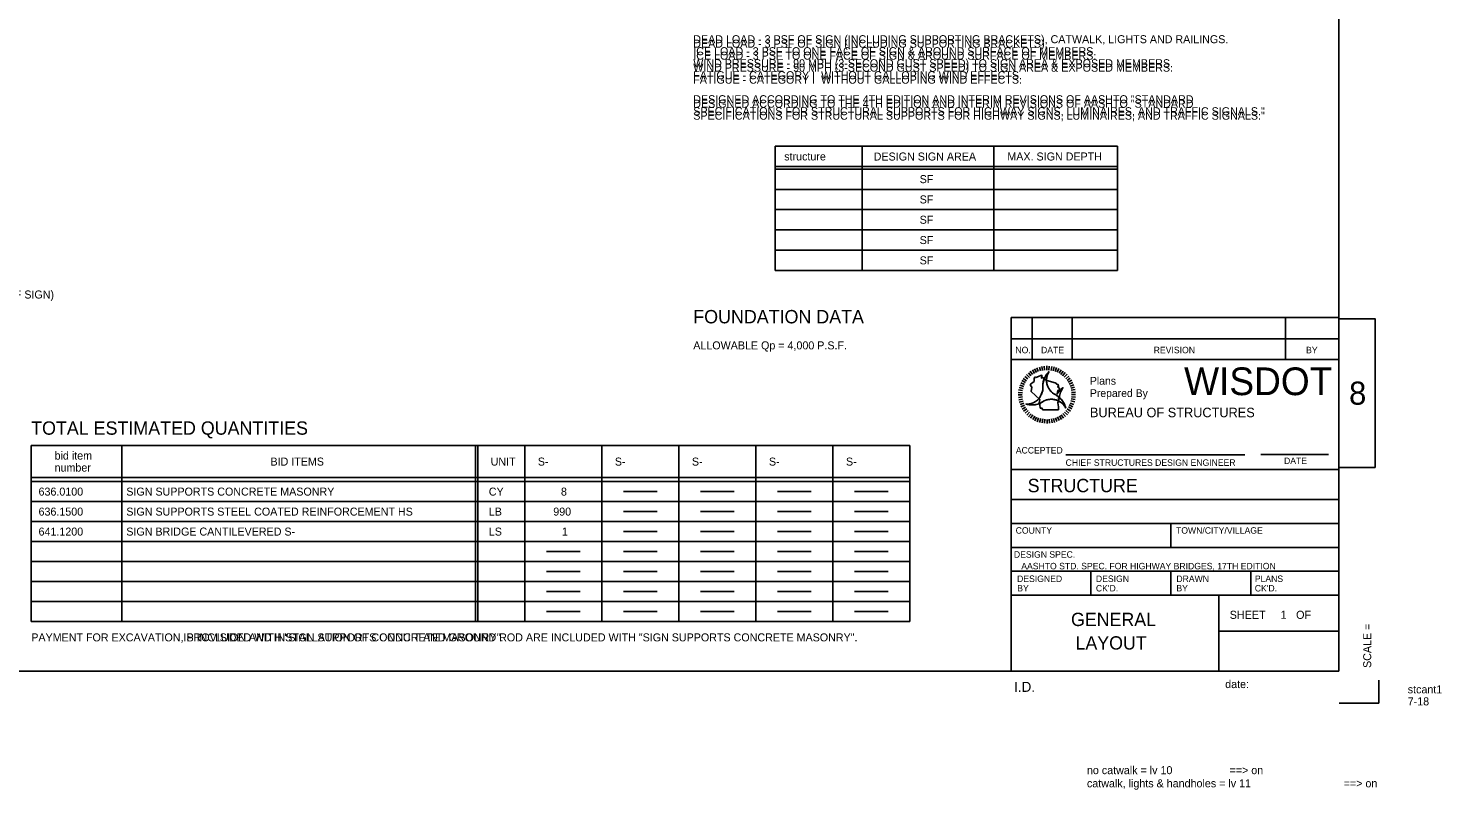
# Model space of a CAD drawing. Extents: x -21 to 58.5, y -15.2 to 40.8.
# Drawn here: x 8.74 to 58.43, y -15.18 to 11.57 of the extents above; entities that cross this region are included whole.
import ezdxf

# ---------------------------------------------------------------- set-up
doc = ezdxf.new("R2010")
doc.units = 0
for name, color, linetype in [('Level 1', 7, 'Continuous'), ('Level 10', 7, 'Continuous'), ('Level 11', 7, 'Continuous'), ('Level 2', 7, 'Continuous')]:
    doc.layers.add(name, color=color, linetype=linetype)

msp = doc.modelspace()

# ---------------------------------------------------------------- linework, layer by layer
at = {"layer": 'Level 1'}
for p, q in [((54.804, -11.023), (54.804, 36.226)), ((43.286, -0.07), (43.286, 1.405)), ((43.286, 1.405), (54.804, 1.405)), ((44.035, -0.07), (44.035, 1.405)), ((45.44, -0.07), (45.44, 1.405)), ((52.931, -0.07), (52.931, 1.405)), ((43.286, 0.657), (54.811, 0.657)), ((43.286, -11.023), (43.286, -0.07)), ((43.286, -0.07), (54.811, -0.07)), ((45.214, -3.422), (51.51, -3.422)), ((52.069, -3.407), (54.447, -3.407)), ((43.286, -3.929), (54.811, -3.929)), ((43.286, -4.982), (54.811, -4.982)), ((43.286, -5.824), (54.811, -5.824)), ((48.905, -5.824), (48.905, -6.667)), ((43.286, -6.667), (54.804, -6.667)), ((43.286, -7.51), (54.804, -7.51)), ((46.095, -7.51), (46.095, -8.353)), ((48.905, -7.51), (48.905, -8.353)), ((51.714, -7.51), (51.714, -8.353)), ((43.286, -8.353), (54.811, -8.353)), ((50.59, -11.023), (50.59, -8.354)), ((50.592, -9.618), (54.804, -9.618)), ((-15.791, -11.023), (54.804, -11.023)), ((56.21, -12.148), (56.21, -11.332)), ((54.821, -12.148), (56.21, -12.148))]:
    msp.add_line(p, q, dxfattribs=at)
msp.add_lwpolyline([(54.804, 1.363), (56.081, 1.363), (56.081, -3.86), (54.804, -3.86)], close=True, dxfattribs=at)
at = {"layer": 'Level 2'}
for p, q in [((34.99, 7.429), (34.99, 3.058)), ((34.99, 7.429), (47.025, 7.429)), ((38.059, 7.429), (38.059, 3.058)), ((42.685, 7.429), (42.685, 3.058)), ((47.025, 7.429), (47.025, 3.058)), ((34.99, 6.715), (47.025, 6.715)), ((34.99, 6.627), (47.025, 6.627)), ((34.99, 5.913), (47.025, 5.913)), ((34.99, 5.199), (47.025, 5.199)), ((34.99, 4.485), (47.025, 4.485)), ((34.99, 3.771), (47.025, 3.771)), ((34.99, 3.058), (47.025, 3.058)), ((44.046, -0.596), (43.965, -0.48)), ((44.11, -0.556), (44.039, -0.432)), ((44.177, -0.519), (44.117, -0.391)), ((44.246, -0.491), (44.198, -0.356)), ((44.317, -0.467), (44.282, -0.331)), ((44.393, -0.45), (44.367, -0.311)), ((44.467, -0.44), (44.455, -0.299)), ((44.542, -0.437), (44.542, -0.294)), ((44.618, -0.439), (44.63, -0.298)), ((44.693, -0.448), (44.718, -0.308)), ((44.767, -0.465), (44.804, -0.327)), ((44.839, -0.487), (44.888, -0.353)), ((44.909, -0.516), (44.969, -0.386)), ((44.976, -0.549), (45.047, -0.427)), ((45.041, -0.59), (45.122, -0.473)), ((43.732, -1.011), (43.598, -0.964)), ((43.76, -0.942), (43.632, -0.881)), ((43.795, -0.874), (43.672, -0.804)), ((43.835, -0.811), (43.719, -0.729)), ((43.881, -0.75), (43.772, -0.659)), ((43.932, -0.694), (43.831, -0.593)), ((43.987, -0.643), (43.895, -0.533)), ((45.101, -0.636), (45.192, -0.527)), ((45.157, -0.686), (45.257, -0.586)), ((45.208, -0.742), (45.316, -0.651)), ((45.254, -0.802), (45.371, -0.72)), ((45.296, -0.865), (45.419, -0.794)), ((45.331, -0.932), (45.459, -0.872)), ((45.36, -1.001), (45.494, -0.953)), ((43.681, -1.309), (43.539, -1.309)), ((43.684, -1.233), (43.543, -1.221)), ((43.685, -1.384), (43.544, -1.396)), ((43.694, -1.158), (43.553, -1.133)), ((43.695, -1.458), (43.556, -1.484)), ((43.709, -1.084), (43.572, -1.048)), ((45.383, -1.073), (45.521, -1.037)), ((45.4, -1.147), (45.54, -1.122)), ((45.402, -1.448), (45.542, -1.473)), ((45.411, -1.222), (45.552, -1.209)), ((45.411, -1.373), (45.554, -1.385)), ((45.415, -1.298), (45.556, -1.298)), ((43.713, -1.532), (43.575, -1.569)), ((43.736, -1.605), (43.602, -1.653)), ((43.765, -1.674), (43.636, -1.734)), ((43.801, -1.741), (43.677, -1.812)), ((43.842, -1.805), (43.725, -1.886)), ((43.887, -1.864), (43.778, -1.955)), ((43.939, -1.919), (43.839, -2.02)), ((43.995, -1.97), (43.904, -2.079)), ((45.109, -1.963), (45.2, -2.072)), ((45.165, -1.912), (45.266, -2.012)), ((45.215, -1.856), (45.324, -1.947)), ((45.26, -1.795), (45.377, -1.877)), ((45.301, -1.732), (45.425, -1.802)), ((45.335, -1.665), (45.464, -1.725)), ((45.364, -1.595), (45.497, -1.643)), ((45.386, -1.523), (45.524, -1.559)), ((44.056, -2.016), (43.974, -2.132)), ((44.119, -2.056), (44.048, -2.179)), ((44.187, -2.091), (44.127, -2.22)), ((44.256, -2.119), (44.208, -2.253)), ((44.329, -2.142), (44.292, -2.279)), ((44.403, -2.157), (44.378, -2.297)), ((44.477, -2.167), (44.465, -2.308)), ((44.553, -2.169), (44.553, -2.311)), ((44.629, -2.166), (44.641, -2.308)), ((44.705, -2.156), (44.729, -2.295)), ((44.778, -2.138), (44.815, -2.276)), ((44.849, -2.115), (44.898, -2.249)), ((44.919, -2.086), (44.98, -2.214)), ((44.986, -2.05), (45.057, -2.173)), ((45.05, -2.01), (45.13, -2.126)), ((8.843, -9.278), (8.843, -3.091)), ((8.843, -9.278), (8.843, -3.091)), ((8.843, -9.278), (8.843, -3.091)), ((8.843, -9.278), (8.843, -3.091)), ((8.843, -9.278), (8.843, -3.091)), ((8.843, -9.278), (8.843, -3.091)), ((8.843, -9.278), (8.843, -3.091)), ((39.731, -3.091), (8.843, -3.091)), ((12.034, -9.278), (12.034, -3.091)), ((12.034, -9.278), (12.034, -3.091)), ((12.034, -9.278), (12.034, -3.091)), ((12.034, -9.278), (12.034, -3.091)), ((12.034, -9.278), (12.034, -3.091)), ((12.034, -9.278), (12.034, -3.091)), ((12.034, -9.278), (12.034, -3.091)), ((12.034, -9.278), (12.034, -3.091)), ((24.459, -9.278), (24.459, -3.091)), ((24.459, -9.278), (24.459, -3.091)), ((24.459, -9.278), (24.459, -3.091)), ((24.459, -9.278), (24.459, -3.091)), ((24.459, -9.278), (24.459, -3.091)), ((24.459, -9.278), (24.459, -3.091)), ((24.459, -9.278), (24.459, -3.091)), ((24.459, -9.278), (24.459, -3.091)), ((24.55, -9.278), (24.55, -3.091)), ((24.55, -9.278), (24.55, -3.091)), ((24.55, -9.278), (24.55, -3.091)), ((24.55, -9.278), (24.55, -3.091)), ((24.55, -9.278), (24.55, -3.091)), ((24.55, -9.278), (24.55, -3.091)), ((24.55, -9.278), (24.55, -3.091)), ((24.55, -9.278), (24.55, -3.091)), ((26.191, -9.278), (26.191, -3.091)), ((28.899, -9.278), (28.899, -3.091)), ((31.607, -9.278), (31.607, -3.091)), ((34.315, -9.278), (34.315, -3.091)), ((37.023, -9.278), (37.023, -3.091)), ((39.731, -9.278), (39.731, -3.091)), ((39.731, -4.216), (8.843, -4.216)), ((39.731, -4.356), (8.843, -4.356)), ((29.661, -4.708), (30.845, -4.708)), ((32.369, -4.708), (33.553, -4.708)), ((35.077, -4.708), (36.261, -4.708)), ((37.785, -4.708), (38.969, -4.708)), ((39.731, -5.06), (8.843, -5.06)), ((29.661, -5.411), (30.845, -5.411)), ((32.369, -5.411), (33.553, -5.411)), ((35.077, -5.411), (36.261, -5.411)), ((37.785, -5.411), (38.969, -5.411)), ((39.731, -5.762), (8.843, -5.762)), ((29.661, -6.114), (30.845, -6.114)), ((32.369, -6.114), (33.553, -6.114)), ((35.077, -6.114), (36.261, -6.114)), ((37.785, -6.114), (38.969, -6.114)), ((39.731, -6.466), (8.843, -6.466)), ((26.953, -6.817), (28.137, -6.817)), ((29.661, -6.817), (30.845, -6.817)), ((32.369, -6.817), (33.553, -6.817)), ((35.077, -6.817), (36.261, -6.817)), ((37.785, -6.817), (38.969, -6.817)), ((39.731, -7.168), (8.843, -7.168)), ((39.731, -7.872), (8.843, -7.872)), ((26.953, -7.52), (28.137, -7.52)), ((29.661, -7.52), (30.845, -7.52)), ((32.369, -7.52), (33.553, -7.52)), ((35.077, -7.52), (36.261, -7.52)), ((37.785, -7.52), (38.969, -7.52)), ((26.953, -8.223), (28.137, -8.223)), ((29.661, -8.223), (30.845, -8.223)), ((32.369, -8.223), (33.553, -8.223)), ((35.077, -8.223), (36.261, -8.223)), ((37.785, -8.223), (38.969, -8.223)), ((39.731, -8.575), (8.843, -8.575)), ((26.953, -8.926), (28.137, -8.926)), ((29.661, -8.926), (30.845, -8.926)), ((32.369, -8.926), (33.553, -8.926)), ((35.077, -8.926), (36.261, -8.926)), ((37.785, -8.926), (38.969, -8.926)), ((39.731, -9.278), (8.843, -9.278))]:
    msp.add_line(p, q, dxfattribs=at)
msp.add_lwpolyline([(44.625, -0.491), (44.535, -0.594), (44.476, -0.702), (44.427, -0.837), (44.4, -0.943), (44.403, -1.073), (44.4, -1.158), (44.375, -1.236), (44.349, -1.295), (44.328, -1.346), (44.297, -1.403), (44.248, -1.46), (44.212, -1.491), (44.144, -1.547), (44.088, -1.575), (44.064, -1.589), (43.99, -1.614), (43.92, -1.631), (43.825, -1.636), (43.812, -1.635), (43.857, -1.646), (43.921, -1.658), (43.979, -1.661), (44.029, -1.663), (44.074, -1.661), (44.133, -1.654), (44.176, -1.645), (44.223, -1.633), (44.282, -1.613), (44.334, -1.589), (44.371, -1.571), (44.45, -1.518), (44.51, -1.494), (44.539, -1.484), (44.59, -1.474), (44.649, -1.469), (44.702, -1.462), (44.751, -1.463), (44.798, -1.472), (44.828, -1.478), (44.87, -1.487), (44.923, -1.505), (44.969, -1.529), (45.026, -1.562), (45.065, -1.594), (45.098, -1.621), (45.122, -1.645), (45.14, -1.666), (45.159, -1.692), (45.178, -1.717), (45.192, -1.735), (45.205, -1.767), (45.203, -1.742), (45.189, -1.703), (45.174, -1.665), (45.157, -1.627), (45.137, -1.585), (45.108, -1.539), (45.087, -1.508), (45.068, -1.484), (45.042, -1.455), (45.016, -1.428), (44.98, -1.395), (44.937, -1.36), (44.89, -1.326), (44.849, -1.302), (44.79, -1.273), (44.753, -1.246), (44.731, -1.227), (44.702, -1.194), (44.678, -1.175), (44.646, -1.137), (44.615, -1.085), (44.599, -1.058), (44.581, -1.016), (44.569, -0.986), (44.559, -0.953), (44.549, -0.921), (44.544, -0.886), (44.539, -0.851), (44.538, -0.794), (44.535, -0.749), (44.543, -0.708), (44.549, -0.676), (44.559, -0.637), (44.571, -0.596), (44.59, -0.56), (44.606, -0.525)], close=True, dxfattribs=at)
msp.add_lwpolyline([(44.394, -1.833), (44.954, -1.834), (44.951, -1.734), (44.93, -1.594), (44.972, -1.474), (44.951, -1.436), (44.99, -1.355), (45.03, -1.216), (45.11, -1.058), (45.03, -1.117), (44.972, -1.196), (44.911, -1.276), (44.93, -1.158), (44.99, -1.137), (44.972, -1.038), (44.93, -1.038), (44.951, -0.958), (44.871, -0.918), (44.871, -0.899), (44.514, -0.798), (44.455, -0.739), (44.394, -0.699), (44.355, -0.718), (44.375, -0.639), (44.375, -0.619), (44.156, -0.699), (44.136, -0.68), (44.095, -0.718), (44.095, -0.838), (43.976, -0.938), (43.976, -0.977), (44.016, -1.038), (43.997, -1.196), (44.294, -1.474), (44.276, -1.594), (44.314, -1.614), (44.294, -1.654), (44.314, -1.773), (44.375, -1.773), (44.394, -1.813), (44.394, -1.833)], dxfattribs=at)
for centre, start, end in [((45.137, -1.02), 134.0652, 186.549), ((44.493, -1.947), 14.0652, 66.549), ((44.013, -0.926), 254.0652, 306.549)]:
    msp.add_arc(centre, 0.737, start, end, dxfattribs=at)
for points in [[(44.783, -1.273), (44.776, -1.259), (44.765, -1.255), (44.758, -1.246), (44.744, -1.242), (44.729, -1.231), (44.728, -1.221), (44.713, -1.21), (44.706, -1.2), (44.699, -1.192), (44.685, -1.179), (44.678, -1.175), (44.674, -1.162), (44.66, -1.152), (44.651, -1.144), (44.646, -1.131), (44.643, -1.117), (44.631, -1.109), (44.618, -1.096), (44.615, -1.085), (44.607, -1.074), (44.601, -1.065), (44.594, -1.051), (44.594, -1.038), (44.588, -1.027), (44.581, -1.014), (44.576, -1), (44.567, -0.986), (44.567, -0.98), (44.56, -0.965), (44.559, -0.953), (44.555, -0.938), (44.549, -0.928), (44.549, -0.917), (44.549, -0.901), (44.543, -0.886), (44.543, -0.872), (44.543, -0.862), (44.535, -0.848), (44.535, -0.833), (44.535, -0.822), (44.535, -0.807), (44.535, -0.792), (44.535, -0.782), (44.535, -0.767), (44.535, -0.754), (44.535, -0.739), (44.543, -0.728), (44.543, -0.715), (44.543, -0.7), (44.549, -0.689), (44.549, -0.676), (44.549, -0.66), (44.555, -0.649), (44.555, -0.634), (44.56, -0.623), (44.567, -0.609), (44.567, -0.596), (44.576, -0.588), (44.581, -0.575), (44.588, -0.561), (44.594, -0.547), (44.596, -0.536), (44.605, -0.524), (44.611, -0.512), (44.616, -0.503), (44.626, -0.491)], [(44.403, -1.101), (44.403, -1.117), (44.4, -1.131), (44.399, -1.144), (44.399, -1.156), (44.391, -1.164), (44.391, -1.179), (44.388, -1.192), (44.386, -1.208), (44.378, -1.221), (44.378, -1.232), (44.371, -1.246), (44.366, -1.258), (44.366, -1.273), (44.36, -1.287), (44.353, -1.298), (44.347, -1.31), (44.339, -1.322), (44.333, -1.329), (44.324, -1.343), (44.321, -1.358), (44.315, -1.368), (44.308, -1.378), (44.301, -1.389), (44.293, -1.4), (44.287, -1.407), (44.276, -1.424), (44.266, -1.436), (44.262, -1.442), (44.25, -1.452), (44.24, -1.462), (44.237, -1.472), (44.221, -1.484), (44.218, -1.487), (44.203, -1.499), (44.193, -1.505), (44.183, -1.515), (44.171, -1.525), (44.161, -1.531), (44.151, -1.539), (44.141, -1.547), (44.13, -1.553), (44.119, -1.557), (44.105, -1.567), (44.093, -1.572), (44.077, -1.581), (44.073, -1.585), (44.06, -1.587), (44.046, -1.596), (44.032, -1.599), (44.021, -1.605), (44.008, -1.608), (43.994, -1.612), (43.982, -1.619), (43.968, -1.619), (43.955, -1.621), (43.944, -1.623), (43.928, -1.628), (43.914, -1.633), (43.899, -1.633), (43.889, -1.633), (43.876, -1.635), (43.862, -1.635), (43.849, -1.635), (43.835, -1.635), (43.825, -1.635), (43.812, -1.635)], [(44.455, -1.518), (44.465, -1.515), (44.48, -1.505), (44.489, -1.502), (44.502, -1.499), (44.514, -1.493), (44.527, -1.487), (44.535, -1.487), (44.549, -1.484), (44.56, -1.484), (44.576, -1.474), (44.588, -1.474), (44.601, -1.472), (44.615, -1.47), (44.626, -1.47), (44.644, -1.47), (44.66, -1.463), (44.674, -1.463), (44.685, -1.462), (44.699, -1.462), (44.713, -1.462), (44.728, -1.462), (44.738, -1.463), (44.749, -1.463), (44.765, -1.47), (44.776, -1.47), (44.794, -1.47), (44.805, -1.472), (44.815, -1.474), (44.828, -1.477), (44.842, -1.484), (44.854, -1.484), (44.868, -1.487), (44.879, -1.491), (44.895, -1.493), (44.907, -1.502), (44.921, -1.505), (44.927, -1.509), (44.942, -1.515), (44.954, -1.519), (44.968, -1.526), (44.976, -1.532), (44.99, -1.539), (45, -1.547), (45.011, -1.553), (45.024, -1.557), (45.037, -1.571), (45.043, -1.574), (45.057, -1.585), (45.068, -1.594), (45.078, -1.6), (45.084, -1.612), (45.098, -1.619), (45.104, -1.628), (45.117, -1.637), (45.123, -1.651), (45.136, -1.655), (45.14, -1.666), (45.15, -1.678), (45.154, -1.689), (45.168, -1.7), (45.173, -1.711), (45.182, -1.721), (45.189, -1.731), (45.194, -1.745), (45.203, -1.756), (45.205, -1.767)]]:
    msp.add_spline(points, degree=3, dxfattribs=at)

# ---------------------------------------------------------------- texts
at = {"layer": 'Level 1'}
for s, height, p in [('FOUNDATION DATA', 0.46945, (32.117, 1.204)), ('NO.', 0.2276, (43.439, 0.153)), ('DATE', 0.2276, (44.34, 0.153)), ('REVISION', 0.2276, (48.3, 0.153)), ('BY', 0.2276, (53.658, 0.153)), ('8', 0.812, (55.17, -1.655)), ('ACCEPTED', 0.2265, (43.455, -3.37)), ('CHIEF STRUCTURES DESIGN ENGINEER', 0.22649, (45.205, -3.803)), ('DATE', 0.2267, (52.883, -3.739)), ('STRUCTURE', 0.4694, (43.872, -4.73)), ('COUNTY', 0.2267, (43.45, -6.187)), ('TOWN/CITY/VILLAGE', 0.22668, (49.087, -6.187)), ('DESIGN SPEC.', 0.22668, (43.388, -7.031)), ('AASHTO STD. SPEC. FOR HIGHWAY BRIDGES, 17TH EDITION', 0.22669, (43.647, -7.439)), ('DESIGNED', 0.2269, (43.499, -7.884)), ('DESIGN', 0.2269, (46.27, -7.884)), ('DRAWN', 0.2267, (49.099, -7.884)), ('PLANS', 0.2267, (51.856, -7.884)), ('BY', 0.2267, (43.506, -8.218)), ("CK'D.", 0.2267, (46.27, -8.218)), ('BY', 0.2269, (49.099, -8.218)), ("CK'D.", 0.2267, (51.856, -8.218)), ('SHEET', 0.2841, (50.973, -9.18)), ('1 ', 0.2812, (52.761, -9.177)), ('OF', 0.2841, (53.307, -9.18)), (' GENERAL ', 0.4676, (45.221, -9.434)), (' LAYOUT ', 0.4676, (45.38, -10.259)), ('I.D.              ', 0.35156, (43.399, -11.745)), ('date:', 0.2805, (50.816, -11.613))]:
    msp.add_text(s, height=height, dxfattribs=at).set_placement(p)
for s, height, rotation, p in [('TOTAL ESTIMATED QUANTITIES', 0.46945, 360, (8.843, -2.71)), ('SCALE =          ', 0.28125, 90, (55.948, -10.906))]:
    msp.add_text(s, height=height, rotation=rotation, dxfattribs=at).set_placement(p)
at = {"layer": 'Level 10'}
for s, height, p in [('DEAD LOAD - 3 PSF OF SIGN (INCLUDING SUPPORTING BRACKETS).', 0.28125, (32.117, 10.892)), ('ICE LOAD - 3 PSF TO ONE FACE OF SIGN & AROUND SURFACE OF MEMBERS.', 0.28125, (32.117, 10.47)), ('WIND PRESSURE - 90 MPH (3-SECOND GUST SPEED) TO SIGN AREA & EXPOSED MEMBERS.', 0.28125, (32.117, 10.048)), ('FATIGUE - CATEGORY I  WITHOUT GALLOPING WIND EFFECTS.', 0.28125, (32.117, 9.626)), ('DESIGNED ACCORDING TO THE 4TH EDITION AND INTERIM REVISIONS OF AASHTO "STANDARD', 0.28125, (32.117, 8.782)), ('SPECIFICATIONS FOR STRUCTURAL SUPPORTS FOR HIGHWAY SIGNS, LUMINAIRES, AND TRAFFIC SIGNALS."', 0.28125, (32.117, 8.36)), ('PAYMENT FOR EXCAVATION IS INCLUDED WITH "SIGN SUPPORTS CONCRETE MASONRY".', 0.28125, (8.848, -9.972)), ('==> on', 0.2816, (50.967, -14.638))]:
    msp.add_text(s, height=height, dxfattribs=at).set_placement(p)
at = {"layer": 'Level 11'}
for s, height, p in [('DEAD LOAD - 3 PSF OF SIGN (INCLUDING SUPPORTING BRACKETS), CATWALK, LIGHTS AND RAILINGS.', 0.28125, (32.117, 11.048)), ('WIND PRESSURE - 90 MPH (3-SECOND GUST SPEED) TO SIGN AREA & EXPOSED MEMBERS.', 0.28125, (32.117, 10.204)), ('ICE LOAD - 3 PSF TO ONE FACE OF SIGN & AROUND SURFACE OF MEMBERS.', 0.28125, (32.117, 10.626)), ('FATIGUE - CATEGORY I  WITHOUT GALLOPING WIND EFFECTS.', 0.28125, (32.117, 9.782)), ('DESIGNED ACCORDING TO THE 4TH EDITION AND INTERIM REVISIONS OF AASHTO "STANDARD', 0.28125, (32.117, 8.939)), ('SPECIFICATIONS FOR STRUCTURAL SUPPORTS FOR HIGHWAY SIGNS, LUMINAIRES, AND TRAFFIC SIGNALS."', 0.28125, (32.117, 8.517)), ('PAYMENT FOR EXCAVATION, PROVISION AND INSTALLATION OF CONDUIT AND GROUND ROD ARE INCLUDED WITH "SIGN SUPPORTS CONCRETE MASONRY".', 0.28125, (8.848, -9.972)), ('==> on', 0.2816, (54.98, -15.1))]:
    msp.add_text(s, height=height, dxfattribs=at).set_placement(p)
at = {"layer": 'Level 2'}
for s, height, p in [('structure', 0.2816, (35.313, 6.929)), ('DESIGN SIGN AREA', 0.28162, (38.458, 6.926)), ('MAX. SIGN DEPTH', 0.28162, (43.157, 6.927)), ('    SF', 0.2816, (39.656, 6.131)), ('    SF', 0.2816, (39.656, 5.418)), ('    SF', 0.2816, (39.656, 4.704)), ('    SF', 0.2816, (39.656, 3.99)), ('    SF', 0.2816, (39.656, 3.276)), ('(LOOKING AT FRONT FACE OF SIGN)', 0.28125, (2.94, 2.077)), ('ALLOWABLE Qp = 4,000 P.S.F.', 0.28125, (32.117, 0.289)), ('WISDOT', 0.9741, (49.37, -1.319)), ('Plans', 0.2738, (46.06, -0.953)), ('Prepared By', 0.27381, (46.06, -1.384)), ('BUREAU OF STRUCTURES', 0.33466, (46.06, -2.095)), ('stcant1      ', 0.28162, (57.23, -11.799)), ('7-18', 0.2816, (57.23, -12.221)), ('no catwalk = lv 10', 0.28162, (45.955, -14.638)), ('catwalk, lights & handholes = lv 11', 0.28162, (45.955, -15.1))]:
    msp.add_text(s, height=height, dxfattribs=at).set_placement(p)
for s, height, p in [('bid item ', 0.2813, (9.667, -3.583)), ('number', 0.2813, (9.667, -4.005)), ('BID ITEMS', 0.2812, (17.255, -3.794)), ('UNIT', 0.2812, (24.995, -3.794)), ('S-      ', 0.2812, (26.653, -3.794)), ('S-      ', 0.2812, (29.361, -3.794)), ('S-      ', 0.2812, (32.069, -3.794)), ('S-      ', 0.2812, (34.777, -3.794)), ('S-      ', 0.2812, (37.485, -3.794)), ('636.0100  ', 0.2812, (9.103, -4.849)), ('SIGN SUPPORTS CONCRETE MASONRY         ', 0.28121, (12.188, -4.849)), (' CY ', 0.2812, (24.826, -4.849)), ('8', 0.281, (27.466, -4.849)), ('636.1500  ', 0.2812, (9.103, -5.552)), ('SIGN SUPPORTS STEEL COATED REINFORCEMENT HS  ', 0.28121, (12.188, -5.552)), (' LB ', 0.2812, (24.826, -5.552)), ('990', 0.2812, (27.196, -5.552)), ('641.1200   ', 0.28121, (9.103, -6.254)), ('SIGN BRIDGE CANTILEVERED S-      ', 0.28121, (12.188, -6.254)), (' LS ', 0.2812, (24.826, -6.254)), ('1', 0.281, (27.501, -6.254))]:
    msp.add_text(s, height=height, rotation=360, dxfattribs=at).set_placement(p)

doc.saveas('drawing.dxf')
